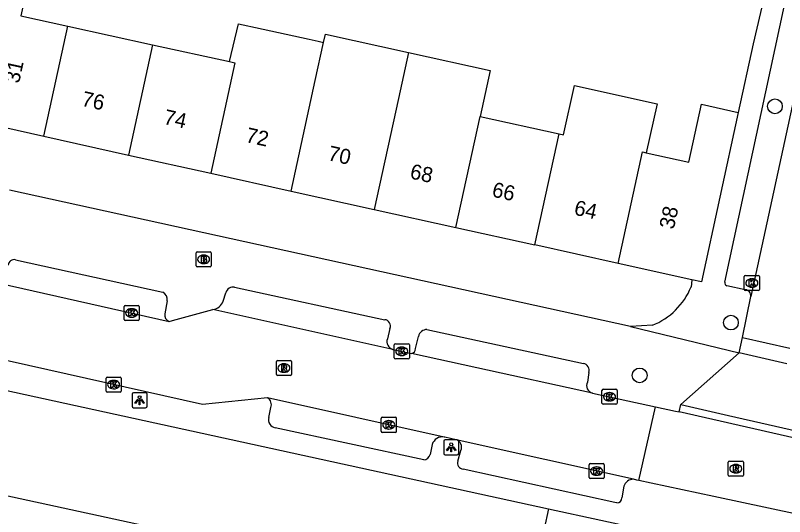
# Model space of a CAD drawing. Extents: x 162172 to 163187, y 382874 to 383684.
# Drawn here: x 162849.7 to 162900.7, y 383122.5 to 383155.7 of the extents above; entities that cross this region are included whole.
import ezdxf

# ---------------------------------------------------------------- set-up
doc = ezdxf.new("R2010")
doc.units = 0
for name, color, linetype in [('IMGEO_Boom', 7, 'Continuous'), ('IMGEO_Brandkraan', 7, 'Continuous'), ('IMGEO_Groenvoorziening', 7, 'Continuous'), ('IMGEO_Kolk', 7, 'Continuous'), ('IMGEO_Lichtpunt', 7, 'Continuous'), ('IMGEO_Muur', 7, 'Continuous'), ('IMGEO_Pand', 7, 'Continuous'), ('IMGEO_Pand_nummerreeks', 7, 'Continuous'), ('IMGEO_Rijbaan_lokaal_open', 7, 'Continuous'), ('IMGEO_Rioolput', 7, 'Continuous'), ('IMGEO_Voetpad_open', 7, 'Continuous')]:
    doc.layers.add(name, color=color, linetype=linetype)

msp = doc.modelspace()

# ---------------------------------------------------------------- linework, layer by layer
at = {"layer": 'IMGEO_Boom'}
for centre in [(162900.09, 383149.702), (162897.168, 383135.339), (162891.11, 383131.831)]:
    msp.add_circle(centre, 0.489, dxfattribs=at)
at = {"layer": 'IMGEO_Brandkraan'}
for p, q in [((162861.667, 383139.113), (162861.667, 383139.965)), ((162861.742, 383140.039), (162862.594, 383140.039)), ((162862.155, 383139.819), (162862.18, 383139.819)), ((162862.668, 383139.965), (162862.668, 383139.113)), ((162862.178, 383139.259), (162862.153, 383139.259)), ((162862.594, 383139.039), (162861.742, 383139.039))]:
    msp.add_line(p, q, dxfattribs=at)
for points in [[(162861.667, 383139.113), (162861.667, 383139.965)], [(162861.742, 383140.039), (162862.594, 383140.039)], [(162862.015, 383139.739), (162862.015, 383139.339), (162862.228, 383139.339)], [(162862.246, 383139.739), (162862.015, 383139.739)], [(162862.668, 383139.965), (162862.668, 383139.113)], [(162862.194, 383139.658), (162862.14, 383139.658), (162862.14, 383139.582)], [(162862.14, 383139.582), (162862.193, 383139.582)], [(162862.202, 383139.506), (162862.14, 383139.506), (162862.14, 383139.425)], [(162862.14, 383139.425), (162862.202, 383139.425)], [(162862.594, 383139.039), (162861.742, 383139.039)]]:
    msp.add_lwpolyline(points, dxfattribs=at)
for centre, radius, start, end in [((162861.744, 383139.963), 0.0765, 91.552, 178.448), ((162861.744, 383139.963), 0.0765, 91.552, 178.448), ((162862.25, 383139.594), 0.145, 59.4692, 91.5367), ((162862.275, 383139.641), 0.0922, 285.5137, 58.1501), ((162862.592, 383139.963), 0.0765, 1.552, 88.448), ((162862.592, 383139.963), 0.0765, 1.552, 88.448), ((162862.195, 383139.62), 0.0379, 267.8285, 90.9355), ((162862.203, 383139.465), 0.0404, 269.8759, 90.5077), ((162862.234, 383139.59), 0.251, 268.6676, 293.5347), ((162862.28, 383139.449), 0.105, 301.3115, 78.989), ((162861.744, 383139.115), 0.0765, 181.552, 268.448), ((162861.744, 383139.115), 0.0765, 181.552, 268.448), ((162862.592, 383139.115), 0.0765, 271.552, 358.448), ((162862.592, 383139.115), 0.0765, 271.552, 358.448)]:
    msp.add_arc(centre, radius, start, end, dxfattribs=at)
for centre, major_axis, ratio, start_param, end_param in [((162862.154, 383139.539), (-0.387, 0.002), 0.722429, 4.712389, 7.853982), ((162862.179, 383139.539), (-0.39, 0.002), 0.717154, 1.570796, 4.712389)]:
    msp.add_ellipse(centre, major_axis=major_axis, ratio=ratio, start_param=start_param, end_param=end_param, dxfattribs=at)
at = {"layer": 'IMGEO_Groenvoorziening'}
for points in [[(162883.631, 383116.338), (162846.104, 383124.475), (162847.668, 383131.141)], [(162885.055, 383122.981), (162883.631, 383116.338)]]:
    msp.add_lwpolyline(points, dxfattribs=at)
at = {"layer": 'IMGEO_Kolk'}
for p, q in [((162898.057, 383137.543), (162898.057, 383138.395)), ((162898.132, 383138.469), (162898.984, 383138.469)), ((162898.545, 383138.249), (162898.57, 383138.249)), ((162899.058, 383138.395), (162899.058, 383137.543)), ((162898.568, 383137.689), (162898.543, 383137.689)), ((162898.984, 383137.469), (162898.132, 383137.469)), ((162856.893, 383135.554), (162856.893, 383136.406)), ((162856.968, 383136.48), (162857.82, 383136.48)), ((162857.381, 383136.26), (162857.406, 383136.26)), ((162857.894, 383136.406), (162857.894, 383135.554)), ((162857.404, 383135.7), (162857.379, 383135.7)), ((162857.82, 383135.48), (162856.968, 383135.48)), ((162874.822, 383133.008), (162874.822, 383133.86)), ((162874.897, 383133.934), (162875.749, 383133.934)), ((162875.31, 383133.714), (162875.335, 383133.714)), ((162875.823, 383133.86), (162875.823, 383133.008)), ((162875.333, 383133.154), (162875.308, 383133.154)), ((162875.749, 383132.934), (162874.897, 383132.934)), ((162855.693, 383130.797), (162855.693, 383131.649)), ((162855.768, 383131.723), (162856.62, 383131.723)), ((162856.181, 383131.503), (162856.206, 383131.503)), ((162856.694, 383131.649), (162856.694, 383130.797)), ((162856.62, 383130.723), (162855.768, 383130.723)), ((162856.204, 383130.943), (162856.179, 383130.943)), ((162888.611, 383129.99), (162888.611, 383130.842)), ((162888.686, 383130.916), (162889.538, 383130.916)), ((162889.099, 383130.696), (162889.124, 383130.696)), ((162889.612, 383130.842), (162889.612, 383129.99)), ((162889.122, 383130.136), (162889.097, 383130.136)), ((162889.538, 383129.916), (162888.686, 383129.916)), ((162873.959, 383128.127), (162873.959, 383128.979)), ((162874.034, 383129.053), (162874.886, 383129.053)), ((162874.96, 383128.979), (162874.96, 383128.127)), ((162874.447, 383128.833), (162874.472, 383128.833)), ((162874.886, 383128.053), (162874.034, 383128.053)), ((162874.47, 383128.273), (162874.445, 383128.273)), ((162887.755, 383125.054), (162887.755, 383125.906)), ((162887.83, 383125.98), (162888.682, 383125.98)), ((162888.756, 383125.906), (162888.756, 383125.054)), ((162888.243, 383125.76), (162888.268, 383125.76)), ((162888.682, 383124.98), (162887.83, 383124.98)), ((162888.266, 383125.2), (162888.241, 383125.2))]:
    msp.add_line(p, q, dxfattribs=at)
for points in [[(162898.057, 383137.543), (162898.057, 383138.395)], [(162898.132, 383138.469), (162898.984, 383138.469)], [(162898.378, 383138.169), (162898.501, 383138.169), (162898.501, 383138.018), (162898.631, 383138.169), (162898.795, 383138.169), (162898.649, 383138.018), (162898.802, 383137.769), (162898.65, 383137.769), (162898.565, 383137.933), (162898.501, 383137.866), (162898.501, 383137.769), (162898.378, 383137.769), (162898.378, 383138.169)], [(162899.058, 383138.395), (162899.058, 383137.543)], [(162898.984, 383137.469), (162898.132, 383137.469)], [(162856.893, 383135.554), (162856.893, 383136.406)], [(162856.968, 383136.48), (162857.82, 383136.48)], [(162857.214, 383136.18), (162857.337, 383136.18), (162857.337, 383136.029), (162857.467, 383136.18), (162857.631, 383136.18), (162857.485, 383136.029), (162857.638, 383135.78), (162857.486, 383135.78), (162857.401, 383135.944), (162857.337, 383135.877), (162857.337, 383135.78), (162857.214, 383135.78), (162857.214, 383136.18)], [(162857.894, 383136.406), (162857.894, 383135.554)], [(162857.82, 383135.48), (162856.968, 383135.48)], [(162874.822, 383133.008), (162874.822, 383133.86)], [(162874.897, 383133.934), (162875.749, 383133.934)], [(162875.143, 383133.634), (162875.266, 383133.634), (162875.266, 383133.483), (162875.396, 383133.634), (162875.56, 383133.634), (162875.414, 383133.483), (162875.567, 383133.234), (162875.415, 383133.234), (162875.33, 383133.398), (162875.266, 383133.331), (162875.266, 383133.234), (162875.143, 383133.234), (162875.143, 383133.634)], [(162875.823, 383133.86), (162875.823, 383133.008)], [(162875.749, 383132.934), (162874.897, 383132.934)], [(162855.693, 383130.797), (162855.693, 383131.649)], [(162855.768, 383131.723), (162856.62, 383131.723)], [(162856.694, 383131.649), (162856.694, 383130.797)], [(162856.014, 383131.423), (162856.137, 383131.423), (162856.137, 383131.272), (162856.267, 383131.423), (162856.431, 383131.423), (162856.285, 383131.272), (162856.438, 383131.023), (162856.286, 383131.023), (162856.201, 383131.187), (162856.137, 383131.12), (162856.137, 383131.023), (162856.014, 383131.023), (162856.014, 383131.423)], [(162856.62, 383130.723), (162855.768, 383130.723)], [(162888.611, 383129.99), (162888.611, 383130.842)], [(162888.686, 383130.916), (162889.538, 383130.916)], [(162888.932, 383130.616), (162889.055, 383130.616), (162889.055, 383130.465), (162889.185, 383130.616), (162889.349, 383130.616), (162889.203, 383130.465), (162889.356, 383130.216), (162889.204, 383130.216), (162889.119, 383130.38), (162889.055, 383130.313), (162889.055, 383130.216), (162888.932, 383130.216), (162888.932, 383130.616)], [(162889.612, 383130.842), (162889.612, 383129.99)], [(162889.538, 383129.916), (162888.686, 383129.916)], [(162873.959, 383128.127), (162873.959, 383128.979)], [(162874.034, 383129.053), (162874.886, 383129.053)], [(162874.96, 383128.979), (162874.96, 383128.127)], [(162874.28, 383128.753), (162874.403, 383128.753), (162874.403, 383128.602), (162874.533, 383128.753), (162874.697, 383128.753), (162874.551, 383128.602), (162874.704, 383128.353), (162874.552, 383128.353), (162874.467, 383128.517), (162874.403, 383128.45), (162874.403, 383128.353), (162874.28, 383128.353), (162874.28, 383128.753)], [(162874.886, 383128.053), (162874.034, 383128.053)], [(162887.755, 383125.054), (162887.755, 383125.906)], [(162887.83, 383125.98), (162888.682, 383125.98)], [(162888.756, 383125.906), (162888.756, 383125.054)], [(162888.076, 383125.68), (162888.199, 383125.68), (162888.199, 383125.529), (162888.329, 383125.68), (162888.493, 383125.68), (162888.347, 383125.529), (162888.5, 383125.28), (162888.348, 383125.28), (162888.263, 383125.444), (162888.199, 383125.377), (162888.199, 383125.28), (162888.076, 383125.28), (162888.076, 383125.68)], [(162888.682, 383124.98), (162887.83, 383124.98)]]:
    msp.add_lwpolyline(points, dxfattribs=at)
for centre, start, end in [((162898.134, 383138.393), 91.552, 178.448), ((162898.134, 383138.393), 91.552, 178.448), ((162898.982, 383138.393), 1.552, 88.448), ((162898.982, 383138.393), 1.552, 88.448), ((162898.134, 383137.545), 181.552, 268.448), ((162898.134, 383137.545), 181.552, 268.448), ((162898.982, 383137.545), 271.552, 358.448), ((162898.982, 383137.545), 271.552, 358.448), ((162856.97, 383136.404), 91.552, 178.448), ((162856.97, 383136.404), 91.552, 178.448), ((162857.818, 383136.404), 1.552, 88.448), ((162857.818, 383136.404), 1.552, 88.448), ((162856.97, 383135.556), 181.552, 268.448), ((162856.97, 383135.556), 181.552, 268.448), ((162857.818, 383135.556), 271.552, 358.448), ((162857.818, 383135.556), 271.552, 358.448), ((162874.899, 383133.858), 91.552, 178.448), ((162874.899, 383133.858), 91.552, 178.448), ((162875.747, 383133.858), 1.552, 88.448), ((162875.747, 383133.858), 1.552, 88.448), ((162874.899, 383133.01), 181.552, 268.448), ((162874.899, 383133.01), 181.552, 268.448), ((162875.747, 383133.01), 271.552, 358.448), ((162875.747, 383133.01), 271.552, 358.448), ((162855.77, 383131.647), 91.552, 178.448), ((162855.77, 383131.647), 91.552, 178.448), ((162856.618, 383131.647), 1.552, 88.448), ((162856.618, 383131.647), 1.552, 88.448), ((162855.77, 383130.799), 181.552, 268.448), ((162855.77, 383130.799), 181.552, 268.448), ((162856.618, 383130.799), 271.552, 358.448), ((162856.618, 383130.799), 271.552, 358.448), ((162888.688, 383130.84), 91.552, 178.448), ((162888.688, 383130.84), 91.552, 178.448), ((162889.536, 383130.84), 1.552, 88.448), ((162889.536, 383130.84), 1.552, 88.448), ((162888.688, 383129.992), 181.552, 268.448), ((162888.688, 383129.992), 181.552, 268.448), ((162889.536, 383129.992), 271.552, 358.448), ((162889.536, 383129.992), 271.552, 358.448), ((162874.036, 383128.977), 91.552, 178.448), ((162874.036, 383128.977), 91.552, 178.448), ((162874.884, 383128.977), 1.552, 88.448), ((162874.884, 383128.977), 1.552, 88.448), ((162874.036, 383128.129), 181.552, 268.448), ((162874.036, 383128.129), 181.552, 268.448), ((162874.884, 383128.129), 271.552, 358.448), ((162874.884, 383128.129), 271.552, 358.448), ((162887.832, 383125.904), 91.552, 178.448), ((162887.832, 383125.904), 91.552, 178.448), ((162888.68, 383125.904), 1.552, 88.448), ((162888.68, 383125.904), 1.552, 88.448), ((162887.832, 383125.056), 181.552, 268.448), ((162887.832, 383125.056), 181.552, 268.448), ((162888.68, 383125.056), 271.552, 358.448), ((162888.68, 383125.056), 271.552, 358.448)]:
    msp.add_arc(centre, 0.0765, start, end, dxfattribs=at)
for centre, major_axis, ratio, start_param, end_param in [((162898.544, 383137.969), (-0.387, 0.002), 0.722429, 4.712389, 7.853982), ((162898.569, 383137.969), (-0.39, 0.002), 0.717154, 1.570796, 4.712389), ((162857.38, 383135.98), (-0.387, 0.002), 0.722429, 4.712389, 7.853982), ((162857.405, 383135.98), (-0.39, 0.002), 0.717154, 1.570796, 4.712389), ((162875.309, 383133.434), (-0.387, 0.002), 0.722429, 4.712389, 7.853982), ((162875.334, 383133.434), (-0.39, 0.002), 0.717154, 1.570796, 4.712389), ((162856.18, 383131.223), (-0.387, 0.002), 0.722429, 4.712389, 7.853982), ((162856.205, 383131.223), (-0.39, 0.002), 0.717154, 1.570796, 4.712389), ((162889.098, 383130.416), (-0.387, 0.002), 0.722429, 4.712389, 7.853982), ((162889.123, 383130.416), (-0.39, 0.002), 0.717154, 1.570796, 4.712389), ((162874.446, 383128.553), (-0.387, 0.002), 0.722429, 4.712389, 7.853982), ((162874.471, 383128.553), (-0.39, 0.002), 0.717154, 1.570796, 4.712389), ((162888.242, 383125.48), (-0.387, 0.002), 0.722429, 4.712389, 7.853982), ((162888.267, 383125.48), (-0.39, 0.002), 0.717154, 1.570796, 4.712389)]:
    msp.add_ellipse(centre, major_axis=major_axis, ratio=ratio, start_param=start_param, end_param=end_param, dxfattribs=at)
at = {"layer": 'IMGEO_Lichtpunt'}
for p, q in [((162857.419, 383130.59), (162857.419, 383129.783)), ((162857.419, 383130.59), (162857.419, 383129.783)), ((162858.321, 383130.685), (162857.513, 383130.685)), ((162858.321, 383130.685), (162857.513, 383130.685)), ((162858.415, 383129.783), (162858.415, 383130.59)), ((162858.415, 383129.783), (162858.415, 383130.59)), ((162857.513, 383129.689), (162858.321, 383129.689)), ((162857.513, 383129.689), (162858.321, 383129.689)), ((162878.106, 383127.457), (162878.106, 383126.65)), ((162878.106, 383127.457), (162878.106, 383126.65)), ((162879.008, 383127.552), (162878.2, 383127.552)), ((162879.008, 383127.552), (162878.2, 383127.552)), ((162879.102, 383126.65), (162879.102, 383127.457)), ((162879.102, 383126.65), (162879.102, 383127.457)), ((162878.2, 383126.556), (162879.008, 383126.556)), ((162878.2, 383126.556), (162879.008, 383126.556))]:
    msp.add_line(p, q, dxfattribs=at)
for points in [[(162857.793, 383130.254), (162857.832, 383130.226), (162857.644, 383129.964), (162857.606, 383129.991), (162857.793, 383130.254)], [(162857.895, 383130.206), (162857.942, 383130.206), (162857.942, 383129.884), (162857.895, 383129.884), (162857.895, 383130.206)], [(162858.005, 383130.226), (162858.043, 383130.253), (162858.23, 383129.991), (162858.191, 383129.963), (162858.005, 383130.226)], [(162878.48, 383127.121), (162878.519, 383127.093), (162878.331, 383126.831), (162878.293, 383126.858), (162878.48, 383127.121)], [(162878.582, 383127.073), (162878.629, 383127.073), (162878.629, 383126.751), (162878.582, 383126.751), (162878.582, 383127.073)], [(162878.692, 383127.093), (162878.73, 383127.12), (162878.917, 383126.858), (162878.878, 383126.83), (162878.692, 383127.093)]]:
    msp.add_lwpolyline(points, dxfattribs=at)
for centre in [(162857.918, 383130.388), (162878.605, 383127.255)]:
    msp.add_circle(centre, 0.0994, dxfattribs=at)
for centre, start, end in [((162857.513, 383130.59), 90, 180), ((162857.513, 383130.59), 90, 180), ((162858.321, 383130.59), 0, 90), ((162858.321, 383130.59), 0, 90), ((162857.513, 383129.783), 180, 270), ((162857.513, 383129.783), 180, 270), ((162858.321, 383129.783), 270, 0), ((162858.321, 383129.783), 270, 360), ((162878.2, 383127.457), 90, 180), ((162878.2, 383127.457), 90, 180), ((162879.008, 383127.457), 0, 90), ((162879.008, 383127.457), 0, 90), ((162878.2, 383126.65), 180, 270), ((162878.2, 383126.65), 180, 270), ((162879.008, 383126.65), 270, 0), ((162879.008, 383126.65), 270, 360)]:
    msp.add_arc(centre, 0.0946, start, end, dxfattribs=at)
at = {"layer": 'IMGEO_Muur'}
msp.add_lwpolyline([(162898.651, 383153.856), (162897.653, 383149.297)], dxfattribs=at)
at = {"layer": 'IMGEO_Pand'}
for points in [[(162848.509, 383160.165), (162850.908, 383159.623), (162850.042, 383155.703), (162853.153, 383155.022)], [(162851.552, 383147.711), (162853.153, 383155.022)], [(162853.153, 383155.022), (162858.783, 383153.79)], [(162863.884, 383152.672), (162864.48, 383155.185), (162864.799, 383155.115), (162865.62, 383154.935), (162869.164, 383154.159), (162869.781, 383154.024), (162870.132, 383153.948)], [(162870.132, 383153.948), (162870.249, 383154.483), (162875.775, 383153.273)], [(162858.783, 383153.79), (162857.179, 383146.466)], [(162858.783, 383153.79), (162863.884, 383152.672)], [(162867.971, 383144.078), (162869.58, 383151.426), (162870.132, 383153.948)], [(162875.775, 383153.273), (162875.105, 383150.216), (162873.493, 383142.856)], [(162875.775, 383153.273), (162881.192, 383152.088), (162880.523, 383149.03)], [(162863.884, 383152.672), (162864.247, 383152.593), (162862.64, 383145.258)], [(162885.772, 383147.881), (162886.065, 383147.817), (162886.778, 383151.075), (162892.265, 383149.874), (162891.553, 383146.616)], [(162891.553, 383146.616), (162894.366, 383146), (162895.21, 383149.856), (162897.653, 383149.297)], [(162846.22, 383148.923), (162851.552, 383147.711)], [(162878.909, 383141.658), (162880.523, 383149.03)], [(162880.523, 383149.03), (162885.772, 383147.881)], [(162897.653, 383149.297), (162895.206, 383138.052), (162894.584, 383138.19)], [(162884.155, 383140.497), (162885.772, 383147.881)], [(162851.552, 383147.711), (162857.179, 383146.466)], [(162857.179, 383146.466), (162862.64, 383145.258)], [(162889.691, 383139.272), (162891.31, 383146.669), (162891.553, 383146.616)], [(162862.64, 383145.258), (162867.971, 383144.078)], [(162867.971, 383144.078), (162873.493, 383142.856)], [(162873.493, 383142.856), (162878.909, 383141.658)], [(162878.909, 383141.658), (162884.155, 383140.497)], [(162889.691, 383139.272), (162884.155, 383140.497)], [(162894.584, 383138.19), (162889.691, 383139.272)]]:
    msp.add_lwpolyline(points, dxfattribs=at)
at = {"layer": 'IMGEO_Rijbaan_lokaal_open'}
for points in [[(162904.903, 383169.786), (162903.644, 383161.345), (162902.633, 383156.139), (162898.486, 383137.076)], [(162866.417, 383130.336), (162862.098, 383129.901), (162845.379, 383133.647), (162827.792, 383137.485), (162825.697, 383137.947)], [(162848.58, 383137.957), (162859.892, 383135.417)], [(162897.935, 383134.342), (162898.486, 383137.076)], [(162859.892, 383135.417), (162860.101, 383135.474), (162862.79, 383136.209)], [(162874.733, 383133.564), (162862.79, 383136.209)], [(162897.714, 383133.338), (162897.935, 383134.342)], [(162897.935, 383134.342), (162901.089, 383133.647)], [(162874.733, 383133.564), (162875.962, 383133.292)], [(162887.978, 383130.662), (162880.296, 383132.332), (162875.962, 383133.292)], [(162900.887, 383132.611), (162897.714, 383133.338)], [(162887.978, 383130.662), (162892.167, 383129.751)], [(162878.142, 383127.739), (162866.417, 383130.336)], [(162891.066, 383124.855), (162892.167, 383129.751)], [(162892.167, 383129.751), (162893.499, 383129.461), (162893.736, 383129.407)], [(162902.668, 383127.387), (162893.736, 383129.407)], [(162878.924, 383127.566), (162878.178, 383127.731), (162878.142, 383127.739)], [(162890.71, 383124.934), (162878.924, 383127.566)], [(162891.066, 383124.855), (162890.923, 383124.886), (162890.71, 383124.934)], [(162903.29, 383122.239), (162896.034, 383123.787), (162891.879, 383124.673), (162891.066, 383124.855)]]:
    msp.add_lwpolyline(points, dxfattribs=at)
at = {"layer": 'IMGEO_Rioolput'}
for p, q in [((162866.998, 383131.896), (162866.998, 383132.748)), ((162867.073, 383132.822), (162867.925, 383132.822)), ((162867.486, 383132.602), (162867.511, 383132.602)), ((162867.999, 383132.748), (162867.999, 383131.896)), ((162867.509, 383132.042), (162867.484, 383132.042)), ((162867.925, 383131.822), (162867.073, 383131.822)), ((162896.992, 383125.214), (162896.992, 383126.066)), ((162897.067, 383126.14), (162897.919, 383126.14)), ((162897.48, 383125.92), (162897.505, 383125.92)), ((162897.993, 383126.066), (162897.993, 383125.214)), ((162897.919, 383125.14), (162897.067, 383125.14)), ((162897.503, 383125.36), (162897.478, 383125.36))]:
    msp.add_line(p, q, dxfattribs=at)
for points in [[(162866.998, 383131.896), (162866.998, 383132.748)], [(162867.073, 383132.822), (162867.925, 383132.822)], [(162867.587, 383132.52), (162867.335, 383132.522), (162867.335, 383132.122)], [(162867.999, 383132.748), (162867.999, 383131.896)], [(162867.335, 383132.122), (162867.459, 383132.122), (162867.459, 383132.284), (162867.47, 383132.284)], [(162867.513, 383132.441), (162867.459, 383132.441), (162867.459, 383132.36)], [(162867.459, 383132.36), (162867.511, 383132.36)], [(162867.517, 383132.255), (162867.588, 383132.122), (162867.728, 383132.122), (162867.663, 383132.248)], [(162867.925, 383131.822), (162867.073, 383131.822)], [(162896.992, 383125.214), (162896.992, 383126.066)], [(162897.067, 383126.14), (162897.919, 383126.14)], [(162897.993, 383126.066), (162897.993, 383125.214)], [(162897.581, 383125.838), (162897.329, 383125.84), (162897.329, 383125.44)], [(162897.329, 383125.44), (162897.453, 383125.44), (162897.453, 383125.602), (162897.464, 383125.602)], [(162897.507, 383125.759), (162897.453, 383125.759), (162897.453, 383125.678)], [(162897.453, 383125.678), (162897.505, 383125.678)], [(162897.511, 383125.573), (162897.582, 383125.44), (162897.722, 383125.44), (162897.657, 383125.566)], [(162897.919, 383125.14), (162897.067, 383125.14)]]:
    msp.add_lwpolyline(points, dxfattribs=at)
for centre, radius, start, end in [((162867.075, 383132.746), 0.0765, 91.552, 178.448), ((162867.075, 383132.746), 0.0765, 91.552, 178.448), ((162867.586, 383132.41), 0.109, 350.3612, 89.416), ((162867.923, 383132.746), 0.0765, 1.552, 88.448), ((162867.923, 383132.746), 0.0765, 1.552, 88.448), ((162867.469, 383132.231), 0.0533, 26.0293, 88.6989), ((162867.495, 383132.549), 0.19, 274.7715, 282.9687), ((162867.519, 383132.345), 0.0964, 77.0061, 93.1865), ((162867.533, 383132.402), 0.0378, 276.6634, 79.6772), ((162867.584, 383132.41), 0.112, 277.5842, 350.9817), ((162867.568, 383132.195), 0.108, 29.5134, 73.7905), ((162867.075, 383131.898), 0.0765, 181.552, 268.448), ((162867.075, 383131.898), 0.0765, 181.552, 268.448), ((162867.923, 383131.898), 0.0765, 271.552, 358.448), ((162867.923, 383131.898), 0.0765, 271.552, 358.448), ((162897.069, 383126.064), 0.0765, 91.552, 178.448), ((162897.069, 383126.064), 0.0765, 91.552, 178.448), ((162897.917, 383126.064), 0.0765, 1.552, 88.448), ((162897.917, 383126.064), 0.0765, 1.552, 88.448), ((162897.463, 383125.549), 0.0533, 26.0293, 88.6989), ((162897.489, 383125.867), 0.19, 274.7715, 282.9687), ((162897.513, 383125.663), 0.0964, 77.0061, 93.1865), ((162897.527, 383125.72), 0.0378, 276.6634, 79.6772), ((162897.58, 383125.728), 0.109, 350.3612, 89.416), ((162897.578, 383125.728), 0.112, 277.5842, 350.9817), ((162897.562, 383125.513), 0.108, 29.5134, 73.7905), ((162897.069, 383125.216), 0.0765, 181.552, 268.448), ((162897.069, 383125.216), 0.0765, 181.552, 268.448), ((162897.917, 383125.216), 0.0765, 271.552, 358.448), ((162897.917, 383125.216), 0.0765, 271.552, 358.448)]:
    msp.add_arc(centre, radius, start, end, dxfattribs=at)
for centre, major_axis, ratio, start_param, end_param in [((162867.485, 383132.322), (-0.387, 0.002), 0.722429, 4.712389, 7.853982), ((162867.51, 383132.322), (-0.39, 0.002), 0.717154, 1.570796, 4.712389), ((162897.479, 383125.64), (-0.387, 0.002), 0.722429, 4.712389, 7.853982), ((162897.504, 383125.64), (-0.39, 0.002), 0.717154, 1.570796, 4.712389)]:
    msp.add_ellipse(centre, major_axis=major_axis, ratio=ratio, start_param=start_param, end_param=end_param, dxfattribs=at)
at = {"layer": 'IMGEO_Voetpad_open'}
for points in [[(162896.768, 383138.028), (162900.715, 383156.409), (162901.688, 383161.501)], [(162899.697, 383158.408), (162898.651, 383153.856), (162897.653, 383149.297)], [(162890.494, 383135.078), (162849.281, 383144.142)], [(162849.682, 383139.515), (162859.456, 383137.357)], [(162894.584, 383138.19), (162894.525, 383137.704)], [(162864.224, 383137.696), (162874.187, 383135.533)], [(162898.118, 383137.516), (162896.898, 383137.774)], [(162863.469, 383136.771), (162863.632, 383137.326)], [(162859.751, 383136.796), (162859.583, 383135.931)], [(162891.954, 383135.159), (162890.494, 383135.078)], [(162890.494, 383135.078), (162897.714, 383133.338)], [(162874.532, 383134.955), (162874.365, 383134.26)], [(162876.994, 383134.882), (162887.374, 383132.623)], [(162876.233, 383133.614), (162876.426, 383134.423)], [(162893.836, 383129.896), (162897.714, 383133.338)], [(162887.744, 383132.032), (162887.642, 383131.386)], [(162847.668, 383131.141), (162885.055, 383122.981)], [(162866.495, 383129.042), (162866.633, 383129.7)], [(162893.736, 383129.407), (162893.836, 383129.896)], [(162893.836, 383129.896), (162897.009, 383129.178), (162902.768, 383127.876), (162902.668, 383127.387)], [(162876.776, 383126.226), (162866.926, 383128.361)], [(162877.346, 383127.244), (162877.204, 383126.59)], [(162879.041, 383126.141), (162879.24, 383126.851)], [(162889.603, 383123.37), (162889.458, 383123.402), (162879.401, 383125.617)], [(162890.067, 383124.468), (162889.938, 383123.696)], [(162885.055, 383122.981), (162895.476, 383120.707), (162893.211, 383110.179)]]:
    msp.add_lwpolyline(points, dxfattribs=at)
for centre, radius, start, end in [((162849.599, 383139.114), 0.409, 78.3023, 174.0023), ((162864.14, 383137.171), 0.531, 80.9505, 163.0603), ((162890.188, 383139.514), 4.699, 292.0716, 337.346), ((162896.973, 383137.973), 0.213, 164.933, 249.2747), ((162859.243, 383136.887), 0.516, 349.8278, 65.6472), ((162898.107, 383137.133), 0.383, 351.4098, 88.406), ((162862.673, 383137.041), 0.841, 277.9976, 341.2307), ((162860.031, 383135.85), 0.455, 169.7978, 252.2281), ((162874.16, 383135.125), 0.409, 335.4251, 86.2397), ((162876.994, 383134.301), 0.581, 90.0041, 167.8792), ((162874.872, 383134.083), 0.537, 160.7194, 255.0146), ((162875.928, 383133.595), 0.305, 276.3372, 3.4938), ((162887.282, 383132.154), 0.478, 345.1543, 78.9436), ((162888.092, 383131.155), 0.506, 152.7968, 256.9941), ((162866.13, 383129.884), 0.536, 339.9577, 57.5596), ((162867.009, 383128.89), 0.536, 163.5532, 261.1057), ((162878.01, 383127.063), 0.688, 78.9586, 164.793), ((162878.788, 383127.078), 0.506, 333.3057, 74.3811), ((162876.76, 383126.678), 0.452, 271.9709, 348.7892), ((162879.41, 383126.009), 0.392, 160.2431, 268.7368), ((162890.682, 383124.297), 0.638, 87.4503, 164.4134), ((162889.579, 383123.73), 0.361, 273.865, 354.5748)]:
    msp.add_arc(centre, radius, start, end, dxfattribs=at)

# ---------------------------------------------------------------- texts
at = {"layer": 'IMGEO_Pand_nummerreeks'}
for s, rotation, p in [('31', 77.7327, (162849.913, 383151.181)), ('76', 347.5242, (162854.013, 383149.747)), ('74', 347.5267, (162859.462, 383148.541)), ('72', 347.5267, (162864.907, 383147.337)), ('70', 347.5267, (162870.362, 383146.13)), ('68', 347.5267, (162875.81, 383144.925)), ('66', 347.5242, (162881.255, 383143.719)), ('64', 347.5267, (162886.704, 383142.514)), ('38', 77.7217, (162893.374, 383141.489))]:
    msp.add_text(s, height=1, rotation=rotation, dxfattribs=at).set_placement(p)

doc.saveas('drawing.dxf')
